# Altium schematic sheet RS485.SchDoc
size A4
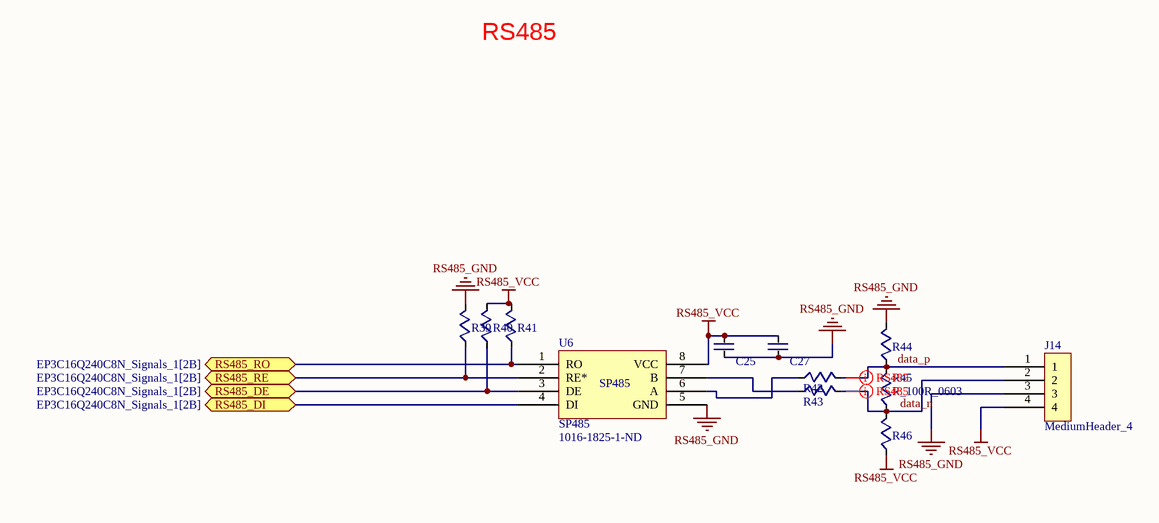
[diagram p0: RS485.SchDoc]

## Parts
C25  100n Cer  [CN-SMD-0805]  (value not drawn)
C27  10n Cer  [CN-SMD-0805]  (value not drawn)
J14  MediumHeader_4  [Medium - Header 4]
R39  R_10K_0603  [RESC_0603]  (value not drawn)
R40  R_10K_0603  [RESC_0603]  (value not drawn)
R41  R_4K99_0603  [RESC_0603]  (value not drawn)
R42  R_10K_0603  [RESC_0603]  (value not drawn)
R43  R_10R_0603  [RESC_0603]  (value not drawn)
R44  R_2K_0603  [RESC_0603]  (value not drawn)
R45  R_100R_0603  [RESC_0603]
R46  R_2K_0603  [RESC_0603]  (value not drawn)
U6  SP485  Supplier Part Number 1: 1016-1825-1-ND  [SOP8]

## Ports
RS485_DE (see EP3C16Q240C8N_Signals_1[2B]), RS485_DI (see EP3C16Q240C8N_Signals_1[2B]), RS485_RE (see EP3C16Q240C8N_Signals_1[2B]), RS485_RO (see EP3C16Q240C8N_Signals_1[2B])

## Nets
RS485_GND: C25.1 C27.1 J14.3 R39.2 R44.2 U6.5(GND)
RS485_VCC: C25.2 C27.2 J14.4 R40.2 R41.2 R46.1 U6.8(VCC)
data_n: J14.2 R43.2 R45.1 R46.2
data_p: J14.1 R42.2 R44.1 R45.2
RS485_DE: R40.1 U6.3(DE) ; port RS485_DE
RS485_DI: U6.4(DI) ; port RS485_DI
RS485_RE: R39.1 U6.2(RE*) ; port RS485_RE
RS485_RO: R41.1 U6.1(RO) ; port RS485_RO
NetR42_1: R42.1 U6.6(A)
NetR43_1: R43.1 U6.7(B)

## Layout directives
differential pair: data_n, data_p

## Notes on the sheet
- RS485

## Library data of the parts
C25 = CAPC0805_104: CAP CER 0.1UF 25V 10% X7R 0805
C27 = CAPC0805_103: CAP CER 10000PF 100V X7R 0805
R39 R40 R42 = RES0603_10K: RES 10.0K OHM 1/10W 1% 0603 SMD
R41 = RES0603_4K99: RES 4.99K OHM 1/10W 1% 0603 SMD
R43 = RES0603_10R: RES 10.0 OHM 1/10W 0603 SMD
R44 R46 = RES0603_2K: RES 2K OHM 1/10W 0603 SMD
R45 = RES0603_100R: RES 100 OHM 1/10W 5% 0603 SMD
U6 = SP485: IC TXRX RS485 HALF DUPLEX 8SOIC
